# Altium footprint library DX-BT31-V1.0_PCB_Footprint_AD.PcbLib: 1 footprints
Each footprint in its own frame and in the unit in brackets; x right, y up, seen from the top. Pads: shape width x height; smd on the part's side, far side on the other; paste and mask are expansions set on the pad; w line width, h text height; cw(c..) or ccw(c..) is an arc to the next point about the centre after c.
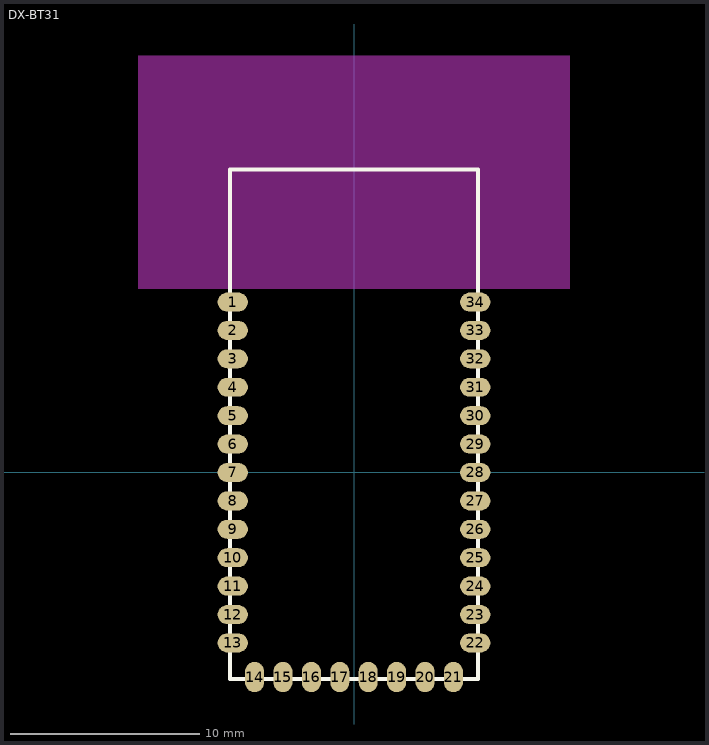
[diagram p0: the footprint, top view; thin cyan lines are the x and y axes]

## DX-BT31 [mm] "DX-BT31"
height 2.3
pads (34):
  rrect100% 1.6x1 smd: 1(-6.4,9) 2(-6.4,7.5) 3(-6.4,6) 4(-6.4,4.5) 5(-6.4,3) 6(-6.4,1.5) 7(-6.4,0) 8(-6.4,-1.5) 9(-6.4,-3) 10(-6.4,-4.5) 11(-6.4,-6) 12(-6.4,-7.5) 13(-6.4,-9) 22(6.4,-9) 23(6.4,-7.5) 24(6.4,-6) 25(6.4,-4.5) 26(6.4,-3) 27(6.4,-1.5) 28(6.4,0) 29(6.4,1.5) 30(6.4,3) 31(6.4,4.5) 32(6.4,6) 33(6.4,7.5) 34(6.4,9)
  rrect100% 1x1.6 smd: 14(-5.25,-10.8) 15(-3.75,-10.8) 16(-2.25,-10.8) 17(-0.75,-10.8) 18(0.75,-10.8) 19(2.25,-10.8) 20(3.75,-10.8) 21(5.25,-10.8)
Top Overlay:
  lines w0.2: -6.55,-10.9 6.55,-10.9 6.55,16 -6.55,16 -6.55,-10.9
Keep-Out Layer:
  region: -11.4,22 -11.4,9.7 11.4,9.7 11.4,22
